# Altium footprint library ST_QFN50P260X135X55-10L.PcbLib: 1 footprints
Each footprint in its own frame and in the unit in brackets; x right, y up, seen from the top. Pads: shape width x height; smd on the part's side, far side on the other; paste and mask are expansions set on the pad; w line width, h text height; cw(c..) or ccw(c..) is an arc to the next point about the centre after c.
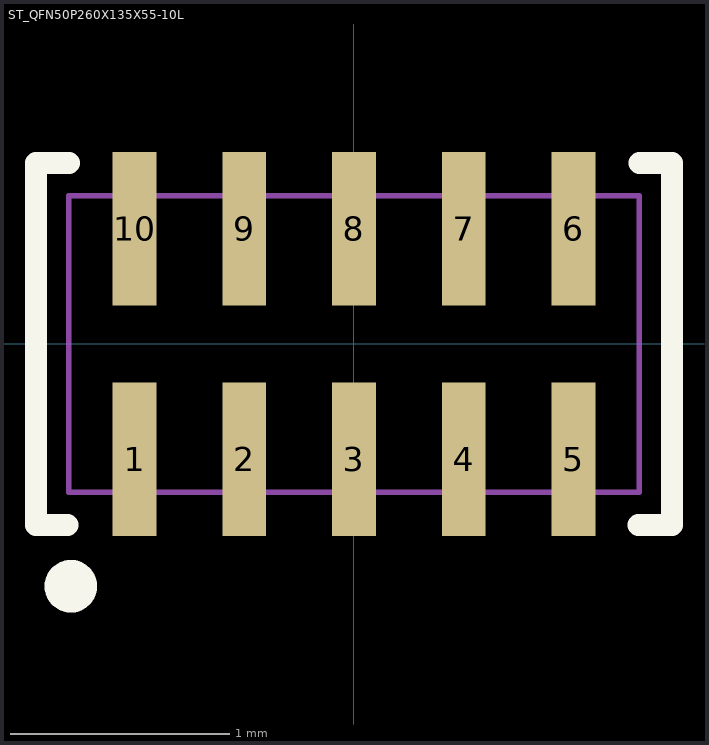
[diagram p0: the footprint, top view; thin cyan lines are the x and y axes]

## ST_QFN50P260X135X55-10L [mm] "ST_QFN50P260X135X55-10L"
pads (10):
  rect 0.2x0.7 smd mask+0.05: 1(-1,-0.525) 2(-0.5,-0.525) 3(0,-0.525) 4(0.5,-0.525) 5(1,-0.525) 6(1,0.525) 7(0.5,0.525) 8(0,0.525) 9(-0.5,0.525) 10(-1,0.525)
Top Overlay:
  circle w0.15: c-1.291,-1.104 r0.045
  lines w0.1: -1.305,-0.825 -1.45,-0.825 -1.45,0.825 -1.3,0.825 ; 1.297,-0.825 1.45,-0.825 1.45,0.825 1.301,0.825
Mechanical 5:
  text "1" at -1.02,-1.05 h0.05
  text "10" at -1.035,1.01 h0.05
  text "2" at -0.52,-1.05 h0.05
  text "9" at -0.495,1.01 h0.05
  text "4" at 0.48,-1.05 h0.05
  text "7" at 0.505,1.01 h0.05
  text "5" at 0.98,-1.05 h0.05
  text "6" at 1.005,1.01 h0.05
  text "3" at -0.02,-1.05 h0.05
  text "8" at 0.005,1.01 h0.05
Mechanical 6:
  lines w0.025: -1.3,-0.675 1.3,-0.675 1.3,0.675 -1.3,0.675 -1.3,-0.675
Mechanical 7:
  lines w0.025: -1.3,-0.675 -1.3,0.675 1.3,0.675 1.3,-0.675 -1.3,-0.675
3D body: height 0.5, standoff 0.02, extent -1.3,-0.675 1.3,0.675
3D body "ST_DFN_260x135x55_10L.STEP": height 0.56, standoff 0.01, extent -1.3,-0.675 1.3,0.675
